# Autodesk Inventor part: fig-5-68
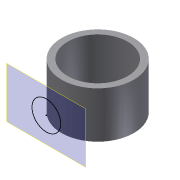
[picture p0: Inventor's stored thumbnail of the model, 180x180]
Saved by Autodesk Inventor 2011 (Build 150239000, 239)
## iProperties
Shininess: 64.0
Length Units: 11269
Angle Units: 11279
Time Units: 11290
Mass Units: 11283
Length Display Precision: 3
Angle Display Precision: 2
Compacted: True
Part Number: fig-5-68
Document SubType Name: Modeling
Created: 2002-12
Designer: deepak
Density: 1 g/cm^3
Density: 0.0
Volumn: 0.0
Area: 0.0
PropertySet Name: Model Information
Control State: 0
Master: False
Checked Out: False
Author: deepak
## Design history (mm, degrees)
sketch "Sketch1"
  geometry: C1 r 23.454 at (0, 0); C2 r 19.43 at (0, 0)
  constraints: 2 centre point, 1 coincident, 1 concentric
extrude "Extrusion1" new body sketch "Sketch1" stored distance "d0" = 30; taper "d1" = 0 deg
workplane "Work Plane1"
workplane "Work Plane2"
sketch "Sketch2"
  geometry: C1 r 9.343 at (0, 0)
  constraints: 1 centre point
body "Solid1"
